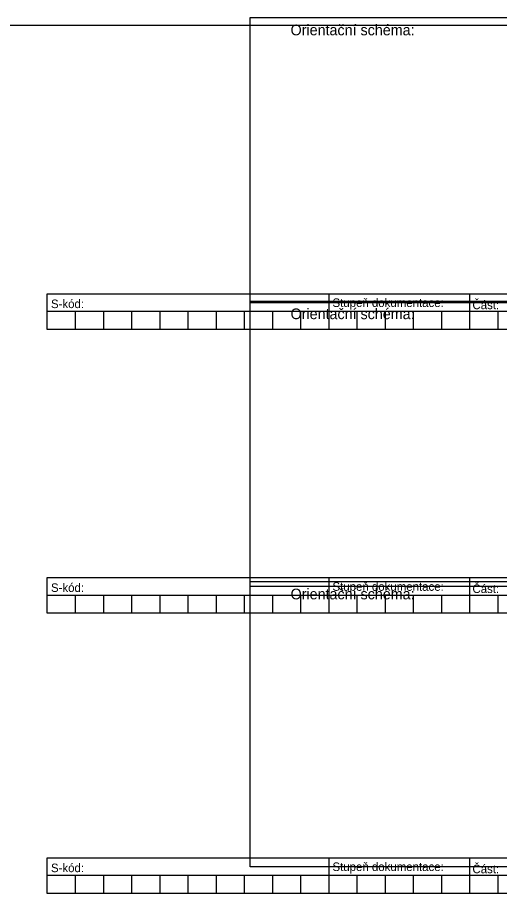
# Model space of a CAD drawing. Extents: x 1391 to 5528, y -6194 to 565.
# Drawn here: x 3139 to 3815, y -2428 to -1200 of the extents above; entities that cross this region are included whole.
import ezdxf

# ---------------------------------------------------------------- set-up
doc = ezdxf.new("R2010")
doc.units = 0
for name, color, linetype in [('Vrstva 11', 7, 'Continuous'), ('Vrstva 2', 7, 'Continuous'), ('Vrstva 8', 7, 'Continuous')]:
    doc.layers.add(name, color=color, linetype=linetype)

# ---------------------------------------------------------------- blocks, each defined once
blk = doc.blocks.new('_U1')
at = {"layer": 'Vrstva 8'}
for p, q in [((-4.55, 0.25), (-4.55, -0.25)), ((-2.575, 0.25), (-2.575, -0.25)), ((8.5, 0), (-8.5, 0)), ((-8.105, 0), (-8.105, -0.25)), ((-7.71, 0), (-7.71, -0.25)), ((-7.315, 0), (-7.315, -0.25)), ((-6.92, 0), (-6.92, -0.25)), ((-6.525, 0), (-6.525, -0.25)), ((-6.13, 0), (-6.13, -0.25)), ((-5.735, 0), (-5.735, -0.25)), ((-5.34, 0), (-5.34, -0.25)), ((-4.945, 0), (-4.945, -0.25)), ((-4.155, 0), (-4.155, -0.25)), ((-3.76, 0), (-3.76, -0.25)), ((-3.365, 0), (-3.365, -0.25)), ((-2.97, 0), (-2.97, -0.25)), ((-2.18, 0), (-2.18, -0.25))]:
    blk.add_line(p, q, dxfattribs=at)
blk.add_lwpolyline([(-8.5, 0.25), (8.5, 0.25), (8.5, -0.25), (-8.5, -0.25)], close=True, dxfattribs=at)
for s, p in [('S-kód:', (-8.445, 0.049)), ('Stupeň dokumentace:', (-4.497, 0.065)), ('Část:', (-2.534, 0.034))]:
    blk.add_text(s, height=0.12, dxfattribs=at).set_placement(p)
blk = doc.blocks.new('_U3')
at = {"layer": 'Vrstva 2'}
blk.add_lwpolyline([(-5.33255, 2.00005), (5.33245, 2.00005), (5.33245, -1.99995), (-5.33255, -1.99995)], close=True, dxfattribs=at)
blk.add_text('Orientační schéma:', height=0.15, dxfattribs=at).set_placement((-4.76755, 1.75005))

msp = doc.modelspace()

# ---------------------------------------------------------------- linework, layer by layer
at = {"layer": 'Vrstva 11'}
msp.add_line((1390.7, -1210.7), (5439, -1210.7), dxfattribs=at)

# ---------------------------------------------------------------- block references
at = {"layer": 'Vrstva 2', "xscale": 100, "yscale": 100}
for p in [(3998.9, -1399.7), (3998.9, -1797.8), (3998.9, -2190.8)]:
    msp.add_blockref('_U3', p, dxfattribs=at)
at = {"layer": 'Vrstva 8', "xscale": 100, "yscale": 100}
for p in [(4030.6, -1612.2), (4030.6, -2010.3), (4030.6, -2403.3)]:
    msp.add_blockref('_U1', p, dxfattribs=at)

doc.saveas('drawing.dxf')
